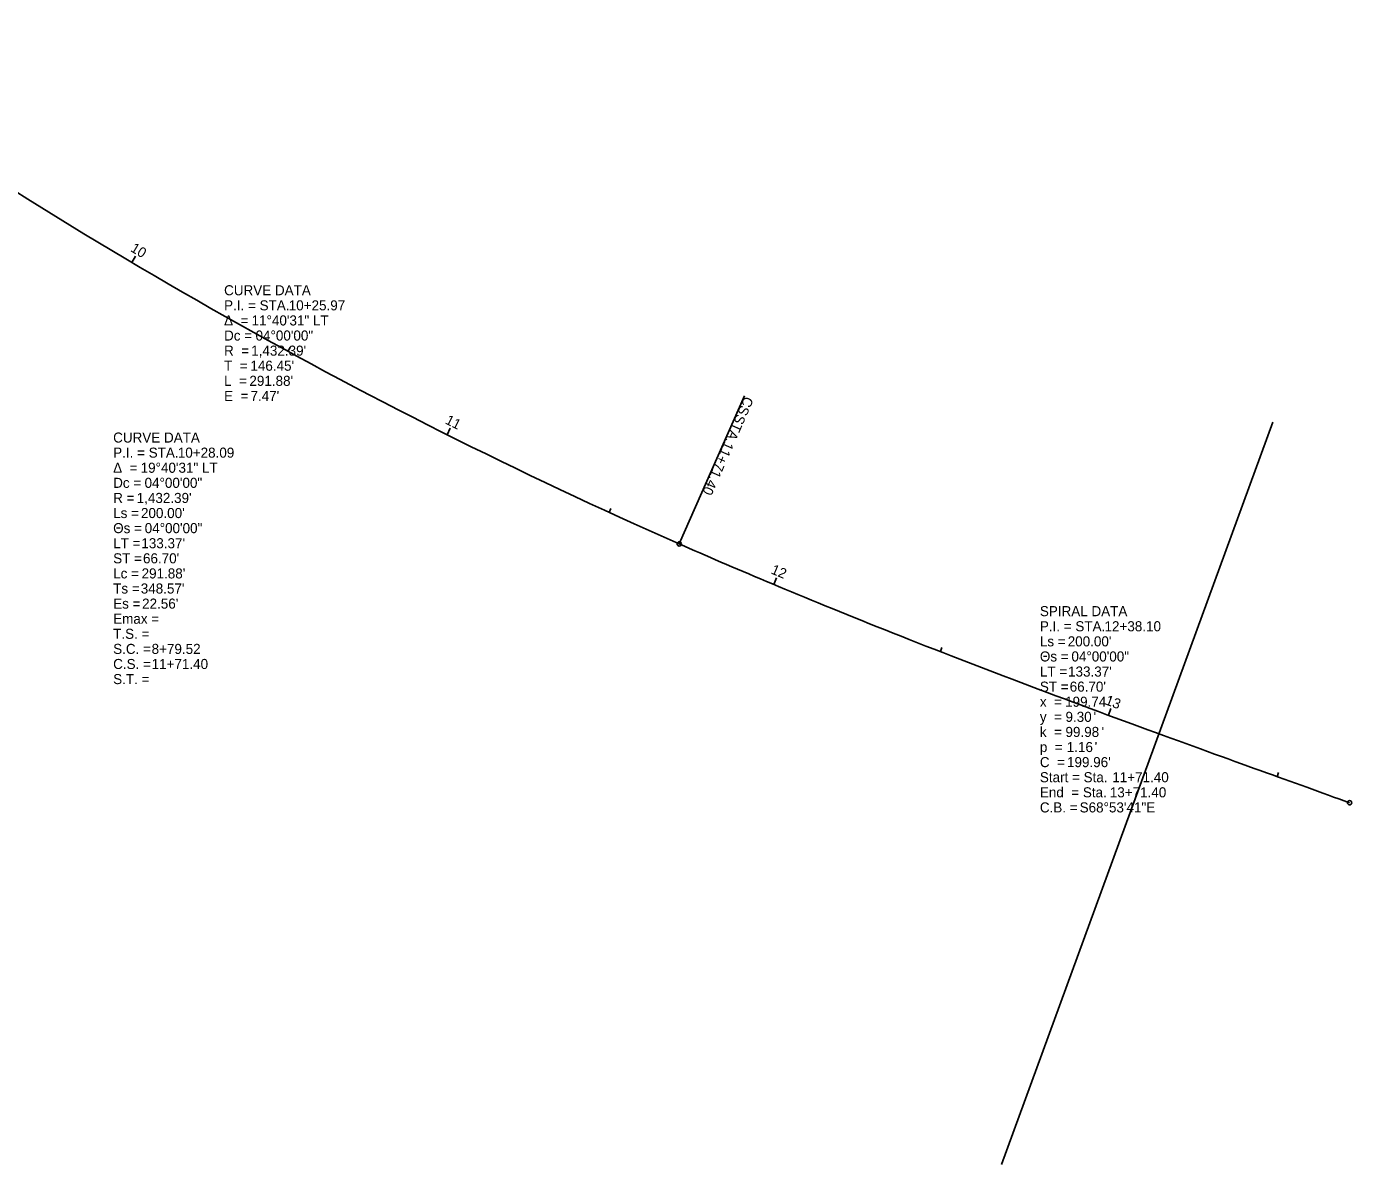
# Model space of a CAD drawing. Extents: x 2331955 to 2333190, y 280152 to 281038.
# Drawn here: x 2332323.6 to 2332691.8, y 280449.3 to 280765.9 of the extents above; entities that cross this region are included whole.
import ezdxf

# ---------------------------------------------------------------- set-up
doc = ezdxf.new("R2010")
doc.units = 0
for name, color, linetype in [('_CIVIL_CONSTRUCTION', 7, 'Continuous'), ('Default', 7, 'Continuous'), ('RW_X_Esmt_SH', 7, 'Continuous'), ('RW_X_Fee_RW', 7, 'Continuous'), ('SV_X_Text', 7, 'Continuous')]:
    doc.layers.add(name, color=color, linetype=linetype)

msp = doc.modelspace()

# ---------------------------------------------------------------- linework, layer by layer
at = {"layer": '_CIVIL_CONSTRUCTION'}
msp.add_arc((2333082.61, 281932.82), 1432.39, 234.55278, 246.22798, dxfattribs=at)
msp.add_open_spline([(2332505.22, 280621.95), (2332512.84, 280618.59), (2332528.15, 280612.01), (2332558.97, 280599.3), (2332597.8, 280584.19), (2332636.89, 280569.75), (2332668.23, 280558.41), (2332683.92, 280552.77), (2332691.76, 280549.95)], degree=3, dxfattribs=at)
at = {"layer": 'Default'}
msp.add_line((2332594.89, 280449.29), (2332670.45, 280655.87), dxfattribs=at)
msp.add_arc((2333082.61, 281932.82), 1432.39, 234.55278, 246.22798, dxfattribs=at)
msp.add_open_spline([(2332505.22, 280621.95), (2332512.84, 280618.59), (2332528.15, 280612.01), (2332558.97, 280599.3), (2332597.8, 280584.19), (2332636.89, 280569.75), (2332668.23, 280558.41), (2332683.92, 280552.77), (2332691.76, 280549.95)], degree=3, dxfattribs=at)
at = {"layer": 'RW_X_Fee_RW'}
msp.add_line((2332505.22, 280621.95), (2332523.36, 280663.13), dxfattribs=at)
for centre in [(2332505.22, 280621.95), (2332691.76, 280549.95)]:
    msp.add_circle(centre, 0.6, dxfattribs=at)
at = {"layer": 'SV_X_Text'}
for p, q in [((2332352.86, 280700.25), (2332353.88, 280701.97)), ((2332396.32, 280675.53), (2332396.9, 280676.59)), ((2332440.62, 280652.35), (2332441.51, 280654.14)), ((2332485.7, 280630.72), (2332486.2, 280631.81)), ((2332531.5, 280610.67), (2332532.27, 280612.52)), ((2332577.88, 280591.99), (2332578.31, 280593.11)), ((2332624.64, 280574.3), (2332625.33, 280576.18)), ((2332671.62, 280557.19), (2332672.03, 280558.32))]:
    msp.add_line(p, q, dxfattribs=at)

# ---------------------------------------------------------------- texts
at = {"layer": 'RW_X_Esmt_SH'}
for s, p in [('CURVE DATA', (2332378.55, 280691.13)), ('P.I. = STA. ', (2332378.55, 280686.93)), ('10+25.97', (2332396.54, 280686.93)), ('Δ  = ', (2332378.55, 280682.73)), ('11°40\'31" LT', (2332386.2, 280682.73)), ('Dc = ', (2332378.55, 280678.53)), ('04°00\'00"', (2332387.3, 280678.53)), ('R  = ', (2332378.55, 280674.33)), ("1,432.39'", (2332386.09, 280674.33)), ('T  = ', (2332378.55, 280670.13)), ("146.45'", (2332385.87, 280670.13)), ('L  = ', (2332378.55, 280665.93)), ("291.88'", (2332385.59, 280665.93)), ('E  = ', (2332378.55, 280661.73)), ("7.47'", (2332385.9, 280661.73)), ('CURVE DATA', (2332347.68, 280650.15)), ('P.I. = STA. ', (2332347.68, 280645.95)), ('10+28.09', (2332365.67, 280645.95)), ('Δ  = ', (2332347.68, 280641.75)), ('19°40\'31" LT', (2332355.32, 280641.75)), ('Dc = ', (2332347.68, 280637.55)), ('04°00\'00"', (2332356.42, 280637.55)), ('R = ', (2332347.68, 280633.35)), ("1,432.39'", (2332354.22, 280633.35)), ('Ls = ', (2332347.68, 280629.15)), ("200.00'", (2332355.42, 280629.15)), ('Θs = ', (2332347.68, 280624.95)), ('04°00\'00"', (2332356.46, 280624.95)), ('LT = ', (2332347.68, 280620.75)), ("133.37'", (2332355.52, 280620.75)), ('ST = ', (2332347.68, 280616.55)), ("66.70'", (2332355.98, 280616.55)), ('Lc = ', (2332347.68, 280612.35)), ("291.88'", (2332355.59, 280612.35)), ('Ts = ', (2332347.68, 280608.15)), ("348.57'", (2332355.36, 280608.15)), ('Es = ', (2332347.68, 280603.95)), ("22.56'", (2332355.73, 280603.95)), ('Emax = ', (2332347.68, 280599.75)), ('SPIRAL DATA', (2332605.58, 280601.85)), ('T.S. = ', (2332347.68, 280595.55)), ('P.I. = STA. ', (2332605.58, 280597.65)), ('12+38.10', (2332623.57, 280597.65)), ('S.C. = ', (2332347.68, 280591.35)), ('8+79.52', (2332358.38, 280591.35)), ('Ls = ', (2332605.58, 280593.45)), ("200.00'", (2332613.33, 280593.45)), ('Θs = ', (2332605.58, 280589.25)), ('04°00\'00"', (2332614.36, 280589.25)), ('C.S. = ', (2332347.68, 280587.15)), ('11+71.40', (2332358.38, 280587.15)), ('LT = ', (2332605.58, 280585.05)), ("133.37'", (2332613.43, 280585.05)), ('S.T. = ', (2332347.68, 280582.95)), ('ST = ', (2332605.58, 280580.85)), ("66.70'", (2332613.88, 280580.85)), ('199.74', (2332612.61, 280576.65)), ("'", (2332624.87, 280576.65)), ('x  = ', (2332605.58, 280576.65)), ('y  = ', (2332605.58, 280572.45)), ('9.30', (2332612.71, 280572.45)), ("'", (2332620.5, 280572.45)), ('k  = ', (2332605.58, 280568.25)), ('99.98', (2332612.71, 280568.25)), ("'", (2332622.73, 280568.25)), ('p  = ', (2332605.58, 280564.05)), ('1.16', (2332613.06, 280564.05)), ("'", (2332620.84, 280564.05)), ('C  = ', (2332605.58, 280559.85)), ("199.96'", (2332613.13, 280559.85)), ('Start = Sta. ', (2332605.58, 280555.65)), ('11+71.40', (2332625.73, 280555.65)), ('End  = Sta. ', (2332605.58, 280551.45)), ('13+71.40', (2332625.04, 280551.45)), ('C.B. = ', (2332605.58, 280547.25)), ('S68°53\'41"E', (2332616.65, 280547.25))]:
    msp.add_text(s, height=2.8, dxfattribs=at).set_placement(p)
at = {"layer": 'RW_X_Fee_RW'}
for s, p in [('CS', (2332523.43, 280663.21)), (' STA. ', (2332521.67, 280659.22)), ('11+71.40', (2332517.91, 280650.69))]:
    msp.add_text(s, height=2.8, rotation=246.228, dxfattribs=at).set_placement(p)
at = {"layer": 'SV_X_Text'}
for s, rotation, p in [('10', 329.372, (2332352.28, 280703.5)), ('11', 333.372, (2332439.86, 280655.53)), ('12', 337.2902, (2332530.53, 280613.79)), ('13', 339.7182, (2332623.56, 280577.37))]:
    msp.add_text(s, height=2.8, rotation=rotation, dxfattribs=at).set_placement(p)

doc.saveas('drawing.dxf')
